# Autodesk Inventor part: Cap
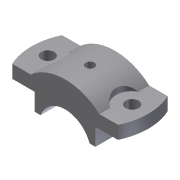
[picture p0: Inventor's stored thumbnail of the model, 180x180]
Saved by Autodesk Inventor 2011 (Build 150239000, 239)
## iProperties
Shininess: 77.0
Angle Display Precision: 2
Document Length Units: 11269
Document Angle Units: 11279
Document Time Units: 11290
Document Mass Units: 11283
Document Length Units Precision: 3
Document Angle Units Precision: 2
Created: 2002-02
Part Number: Cap
Document SubType Name: Modeling
Designer: ***
Density: 1 g/cm^3
Density: 0.0
Volumn: 0.0
Area: 0.0
PropertySet Name: Model Information
Control State: 0
Master: False
Checked Out: False
Author: ***
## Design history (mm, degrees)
sketch "Sketch2"
  geometry: L1 (22.656, 22.99)-(28.029, 22.99); L2 (28.029, 22.99)-(28.029, 38.99); L3 (28.029, 38.99)-(54.029, 38.99); L4 (54.029, 38.99)-(54.029, 50.99); L5 (54.029, 50.99)-(31.778, 50.99); L6 (-22.599, 22.99)-(-27.971, 22.99); L7 (-27.971, 22.99)-(-27.971, 38.99); L8 (-27.971, 38.99)-(-53.971, 38.99); L9 (-53.971, 38.99)-(-53.971, 50.99); L10 (-53.971, 50.99)-(-31.72, 50.99); A1 r 24 centre (0.029, 14.99) between (22.656, 22.99) and (-22.599, 22.99); A2 r 48 centre (0.029, 14.99) between (31.778, 50.99) and (-31.72, 50.99)
  constraints: 20 end point, 5 equal length, 4 parallel, 4 perpendicular, 4 point on circle, 2 centre point, 1 coincident, 1 horizontal, 1 point on line
  dimensions: "d0" = 24 radius of A1; "d1" = 8 distance from line of L1 A1.centre; "d2" = 12 distance of L8.end L9.end; "d3" = 16 distance of L6.end L7.end; "d4" = 48 radius of A2; "d5" = 108 distance between parallel lines of L9 L4; "d6" = 56 distance between parallel lines of L7 L2
extrude "Extrusion1" new body sketch "Sketch2" stored distance "d7" = 46; taper "d8" = 0 deg
sketch "Sketch3"
  geometry: L1 (17.108, 0)-(40.349, 0); L2 (40.349, 0)-(40.349, -46); L3 (40.349, -46)-(17.108, -46); L4 (0, -46)-(22.251, -46) reference; L5 (22.251, 0)-(0, 0) reference; L6 (22.251, 0)-(22.251, -46) reference; A1 r 54 centre (-31.749, -23) between (17.108, -46) and (17.108, 0)
  constraints: 6 end point, 2 collinear, 2 point on circle, 1 centre point, 1 horizontal, 1 parallel, 1 perpendicular, 1 vertical alignment
  dimensions: "d9" = 54 radius of A1; "d10" = 54 distance from line of L6 A1.centre
extrude "Extrusion2" cut sketch "Sketch3" stored distance "d11" = 46; taper "d12" = 0 deg
sketch "Sketch4"
  geometry: L1 (17.108, 46)-(0, 46) reference; A1 r 54 centre (-31.749, 23) between (17.108, 0) and (17.108, 46) reference; 1 further point
  dimensions: "d13" = 23 distance from line of L1 point (7.251, 23); "d14" = 39 distance of A1.centre point (7.251, 23)
hole "Hole1" sketch "Sketch4" diameter "d15" = 30; stored, may be unused: countersink angle "d19" = 82 deg, drill point angle "d21" = 118 deg; dims "d16" = 6, "d17" = 4, "d18" = 2, "d20" = 8
hole "Hole2" sketch "Sketch4" diameter "d22" = 12; stored, may be unused: countersink angle "d26" = 82 deg, drill point angle "d28" = 118 deg; dims "d23" = 6, "d24" = 4, "d25" = 2, "d27" = 8
workplane "Work Plane1"
mirror "Mirror1"
workplane "Work Plane2"
sketch "Sketch5"
  geometry: L1 (31.749, -23)-(-31.749, -23) reference; C1 r 6 at (39, 0) reference; 1 further point
  dimensions: "d30" = 23 distance from line of L1 point (0, 0); "d31" = 39 distance of C1.centre point (0, 0)
hole "Hole3" sketch "Sketch5" at (0, 0) diameter "d32" = 6; stored, may be unused: countersink angle "d36" = 82 deg, drill point angle "d38" = 118 deg; dims "d33" = 6, "d34" = 8, "d35" = 16, "d37" = 8
body "Solid1"
other parameters: "d29" = -54
